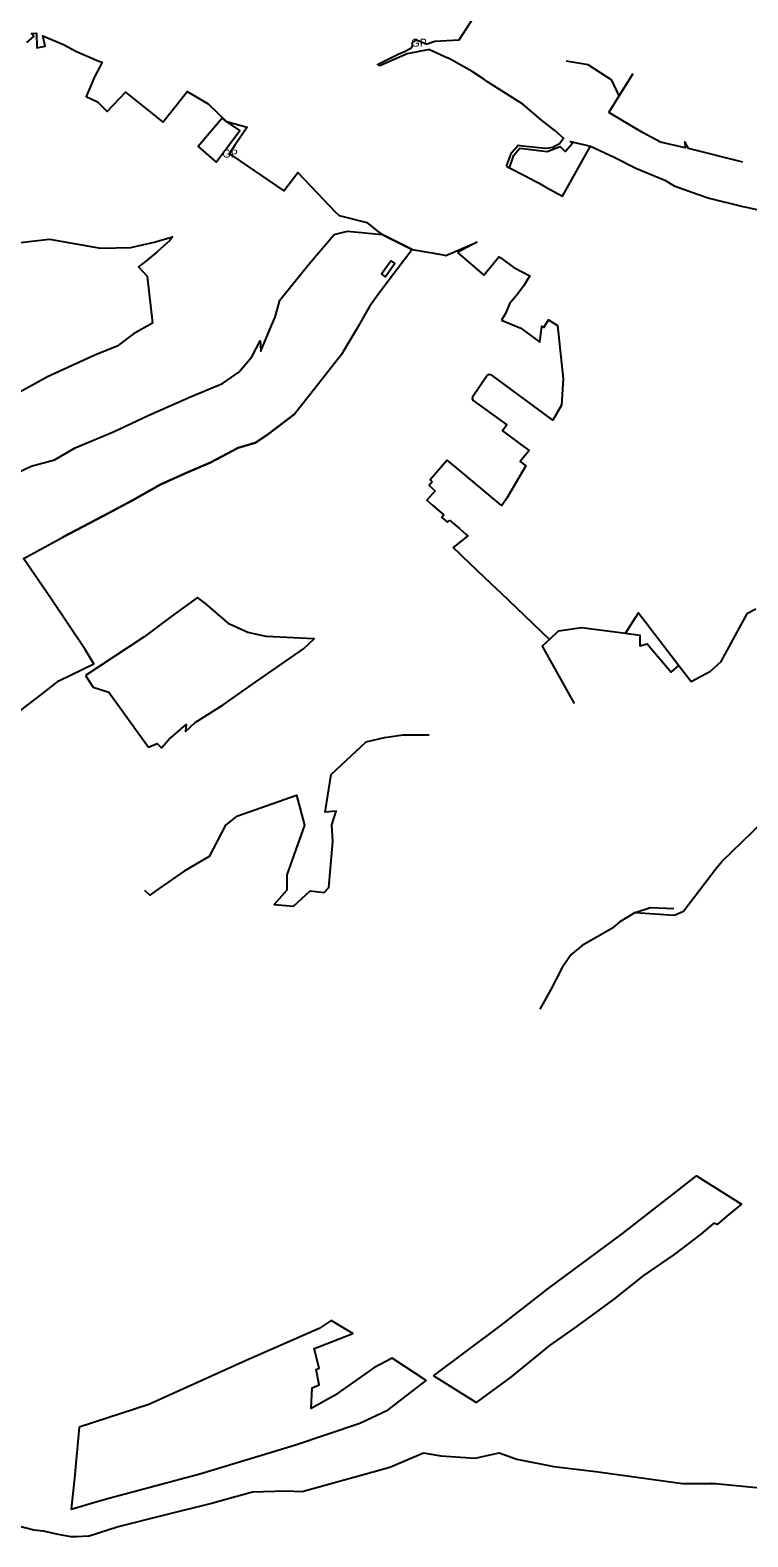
# Model space of a CAD drawing. Extents: x -617038 to -609441, y -1109294 to -1104285.
# Drawn here: x -614251 to -613353, y -1108912 to -1107029 of the extents above; entities that cross this region are included whole.
import ezdxf

# ---------------------------------------------------------------- set-up
doc = ezdxf.new("R2010")
doc.units = 0
for name, color, linetype in [('BOD_SET', 7, 'Continuous'), ('GRA_ZV', 7, 'Continuous'), ('LES_ZV', 7, 'Continuous'), ('OVNE_PRE', 7, 'Continuous'), ('OVNE_SET', 7, 'Continuous'), ('OVNI_PRE', 7, 'Continuous'), ('OVNI_SET', 7, 'Continuous')]:
    doc.layers.add(name, color=color, linetype=linetype)

msp = doc.modelspace()

# ---------------------------------------------------------------- linework, layer by layer
at = {"layer": 'BOD_SET'}
for p, q in [((-613398.7, -1108845.2), (-613397.7, -1108846.2)), ((-613398.7, -1108846.2), (-613397.7, -1108845.2)), ((-613997, -1108862.2), (-613996, -1108863.2)), ((-613997, -1108863.2), (-613996, -1108862.2))]:
    msp.add_line(p, q, dxfattribs=at)
at = {"layer": 'GRA_ZV'}
msp.add_line((-613772.9, -1107303.5), (-613810.3, -1107284.9), dxfattribs=at)
for points in [[(-613651.2, -1107201.3), (-613645.7, -1107185.5), (-613638.3, -1107177), (-613603.8, -1107180.9), (-613587.7, -1107174.8), (-613581.2, -1107181), (-613572.1, -1107170.6), (-613574.6, -1107168.4), (-613549.9, -1107174.4)], [(-613651.2, -1107201.3), (-613631.4, -1107211.5), (-613618.8, -1107218.2), (-613614.7, -1107220.4), (-613607.6, -1107224.6), (-613595.7, -1107231.1), (-613584.8, -1107237), (-613549.9, -1107174.4)], [(-614124.8, -1107300.9), (-614095.3, -1107294.4), (-614072.7, -1107287.9), (-614075.7, -1107292.2), (-614091.9, -1107306.5), (-614103.9, -1107316.5), (-614104.1, -1107316.7), (-614114.9, -1107325.3), (-614104.4, -1107337), (-614097.5, -1107395.5), (-614121.2, -1107409.1), (-614141.8, -1107424.2), (-614169.6, -1107435.4), (-614228.7, -1107462.6), (-614284, -1107493), (-614317.4, -1107507.8), (-614348.5, -1107523.2), (-614355.3, -1107445.9), (-614385, -1107362.8)], [(-614249.3, -1107574.4), (-614220.3, -1107566.5), (-614194.3, -1107551.4), (-614145.6, -1107530.8), (-614103, -1107511.2), (-614049.2, -1107487.4), (-614009.9, -1107470.9), (-613989.5, -1107457), (-613973.2, -1107437.5), (-613962.7, -1107417.8), (-613962.2, -1107430.5), (-613948.7, -1107398.4), (-613944.3, -1107388), (-613938.1, -1107366.9), (-613901.7, -1107321.4), (-613870.3, -1107284.6), (-613853.6, -1107280.7), (-613810.3, -1107284.9)], [(-614385, -1107362.8), (-614357.8, -1107344.4), (-614321.6, -1107319.4), (-614303.3, -1107308.5), (-614263.2, -1107294.7), (-614226.4, -1107290.8), (-614162.4, -1107301.9), (-614124.8, -1107300.9)], [(-613772.9, -1107303.5), (-613811.8, -1107355.2), (-613826.1, -1107374.8), (-613841.6, -1107402)], [(-613811, -1107334.1), (-613799.5, -1107317.6), (-613794.5, -1107320.9), (-613806, -1107337.6), (-613811, -1107334.1)], [(-613841.6, -1107402), (-613861.2, -1107434.9), (-613894.7, -1107477.2), (-613920.1, -1107509.3), (-613954.6, -1107535.6), (-613969, -1107545), (-613990.3, -1107551.4), (-614024.9, -1107569.6), (-614054.2, -1107582.3), (-614087.7, -1107597.1), (-614122.3, -1107616.8), (-614159.8, -1107636.6), (-614209.6, -1107663)], [(-614313, -1107860.8), (-614319, -1107819.2), (-614325.7, -1107759.9), (-614327.7, -1107742.8), (-614328.3, -1107737.2), (-614331.9, -1107705.2), (-614344, -1107630.5), (-614305.7, -1107604), (-614277.2, -1107587.8), (-614249.3, -1107574.4)], [(-614313, -1107860.8), (-614284.8, -1107896.9), (-614248.1, -1107868.5), (-614241.5, -1107863.4), (-614214.8, -1107842.7), (-614171, -1107821.3), (-614181.8, -1107803.4), (-614224.9, -1107738.9), (-614258.9, -1107689.8), (-614255.5, -1107688), (-614209.6, -1107663)], [(-614181.3, -1107835.8), (-614171.7, -1107850.6), (-614152.2, -1107856.8), (-614102.5, -1107925.4), (-614091.5, -1107921.1), (-614086.4, -1107926.2), (-614077.3, -1107915.8), (-614055.4, -1107897.3), (-614056.3, -1107906.1), (-614044.2, -1107894.7), (-614009.1, -1107872.4), (-613968.3, -1107843.9), (-613908.8, -1107802.4), (-613895.4, -1107790.2), (-613955.3, -1107787.3), (-613978.2, -1107782.3), (-614001.1, -1107771.7), (-614031.4, -1107746.1), (-614041.2, -1107738.6), (-614074.8, -1107762.7), (-614107.8, -1107787.5), (-614181.3, -1107835.8)], [(-613746.2, -1108711.3), (-613662, -1108648.3), (-613609, -1108607.1), (-613603.2, -1108602.6), (-613510.1, -1108533.7), (-613438.5, -1108478), (-613417.3, -1108461.3), (-613360.7, -1108496.7), (-613379, -1108511.7), (-613391.3, -1108521.8), (-613395.4, -1108520.3), (-613411.8, -1108534.1), (-613445, -1108559.3), (-613483.4, -1108585.7), (-613520.6, -1108615.3), (-613559.9, -1108643.9), (-613570.3, -1108651.5), (-613601, -1108673.2), (-613648.9, -1108712.3), (-613692.9, -1108744.5), (-613746.2, -1108711.3)], [(-614189.3, -1108775.3), (-614195.1, -1108839.2), (-614199.1, -1108877.8), (-614166.9, -1108868.2), (-614156.9, -1108865.3), (-614038.3, -1108833.4), (-613920.1, -1108797.7), (-613838.2, -1108770.2), (-613802.8, -1108753.7), (-613755.3, -1108716.9), (-613797.7, -1108689.2), (-613820.6, -1108701.3), (-613870.1, -1108735.6), (-613899, -1108752.1), (-613898, -1108726.1), (-613889.2, -1108722.5), (-613892.9, -1108703), (-613888.9, -1108701.5), (-613895.4, -1108676.8), (-613890.9, -1108675.1), (-613847.1, -1108658.1), (-613874, -1108641.9), (-613889, -1108652), (-613980.4, -1108692.1), (-614102.3, -1108747.1), (-614189.3, -1108775.3)]]:
    msp.add_lwpolyline(points, dxfattribs=at)
at = {"layer": 'LES_ZV'}
for p, q in [((-613513.9, -1107111.4), (-613496.2, -1107083.7)), ((-613526.9, -1107132.4), (-613513.9, -1107111.4)), ((-613359, -1107194.4), (-613427.3, -1107177.5))]:
    msp.add_line(p, q, dxfattribs=at)
for points in [[(-613513.9, -1107111.4), (-613523.2, -1107092.1), (-613552.8, -1107072.6), (-613580.2, -1107068.1)], [(-613427.3, -1107177.5), (-613431.8, -1107168.8), (-613431.2, -1107176.5), (-613462.2, -1107169.3), (-613484.8, -1107157.4), (-613526.9, -1107132.4)], [(-614209.6, -1107663), (-614159.8, -1107636.6), (-614122.3, -1107616.8), (-614087.7, -1107597.1), (-614054.2, -1107582.3), (-614024.9, -1107569.6), (-613990.3, -1107551.4), (-613969, -1107545), (-613954.6, -1107535.6), (-613920.1, -1107509.3)], [(-613601.1, -1107790.8), (-613610.2, -1107799.3), (-613570.3, -1107871.1)], [(-613505.9, -1107783.2), (-613488.1, -1107785.5), (-613487.9, -1107798.9), (-613478.9, -1107796.4), (-613448.8, -1107831.8), (-613439.2, -1107823.4)], [(-613991.9, -1108011.5), (-613917.4, -1107985.5), (-613907.5, -1108022.9), (-613929.4, -1108085.1), (-613929.4, -1108104), (-613945.2, -1108121.9), (-613921.3, -1108124), (-613900.5, -1108105.1), (-613882.9, -1108107.3), (-613877, -1108100.7), (-613872, -1108043.3), (-613873.2, -1108022.7), (-613868, -1108005.4), (-613881.4, -1108006.9), (-613873.9, -1107959.7), (-613830.5, -1107919), (-613807.5, -1107913.2), (-613784.2, -1107909.9), (-613774.4, -1107910), (-613751.6, -1107910.2)], [(-613991.9, -1108011.5), (-614006.3, -1108022.8), (-614026.7, -1108062.3), (-614058.1, -1108080.4), (-614089, -1108102), (-614096.1, -1108107.1), (-614099, -1108109.2)], [(-613493.8, -1108132.3), (-613444.7, -1108135.3), (-613433.4, -1108130.4), (-613393.4, -1108077.9), (-613385.5, -1108068.5), (-613333.6, -1108018.2)], [(-614099, -1108109.2), (-614100.9, -1108110.6), (-614107.2, -1108104.4)], [(-613493.8, -1108132.3), (-613513.1, -1108143.8), (-613523.2, -1108152), (-613560.2, -1108173.4), (-613574.5, -1108185.1), (-613585.7, -1108201.6), (-613599.2, -1108228.4), (-613612.9, -1108252.7)], [(-613493.8, -1108132.3), (-613474.7, -1108126), (-613445.7, -1108127)]]:
    msp.add_lwpolyline(points, dxfattribs=at)
at = {"layer": 'OVNE_PRE'}
for points in [[(-614178.1, -1108911.6), (-614141.6, -1108899.8), (-614080.3, -1108884.5), (-614024.9, -1108870.8), (-613996.5, -1108862.7), (-613972.5, -1108855.9), (-613930.6, -1108854.9), (-613910.5, -1108855.5), (-613800.7, -1108825.1), (-613758.7, -1108807.5)], [(-613758.7, -1108807.5), (-613736.9, -1108811.3), (-613694, -1108814.2), (-613664.1, -1108807.3), (-613641.8, -1108815.1), (-613595.5, -1108824.5), (-613560.4, -1108828.7), (-613540, -1108831.2), (-613434.6, -1108845.7), (-613398.2, -1108845.7), (-613393.4, -1108845.7), (-613316.5, -1108853.3)], [(-614234, -1108905.2), (-614245.8, -1108903.9), (-614283.2, -1108894.6)]]:
    msp.add_lwpolyline(points, dxfattribs=at)
at = {"layer": 'OVNE_SET'}
msp.add_line((-614215.6, -1108909.3), (-614234, -1108905.2), dxfattribs=at)
msp.add_lwpolyline([(-614178.1, -1108911.6), (-614192.4, -1108912.2), (-614199.2, -1108912.4), (-614215.6, -1108909.3)], dxfattribs=at)
at = {"layer": 'OVNI_PRE'}
for points in [[(-614004.8, -1107143.4), (-614010.5, -1107139.5), (-614040.3, -1107174.9), (-614017.8, -1107194.6), (-613988.3, -1107154.7), (-614004.8, -1107143.4)], [(-613662.8, -1107313.7), (-613645.6, -1107325.9), (-613625.7, -1107336.4), (-613633.5, -1107349.4), (-613641, -1107359.3), (-613651, -1107371.3), (-613656, -1107383.5), (-613660.9, -1107391.9)], [(-613743.8, -1107605), (-613754.3, -1107617), (-613746.9, -1107623.4)], [(-613733.2, -1107635.3), (-613735.7, -1107638.3), (-613728.5, -1107644.5), (-613726, -1107641.6)]]:
    msp.add_lwpolyline(points, dxfattribs=at)
at = {"layer": 'OVNI_SET'}
for p, q in [((-613764.1, -1107042.9), (-613754.3, -1107047.1)), ((-613752.7, -1107046.6), (-613754.3, -1107047.1)), ((-613751.1, -1107053.6), (-613727.5, -1107064.3)), ((-613654.8, -1107199.6), (-613651.2, -1107201.3)), ((-613746.9, -1107623.4), (-613734.9, -1107633.8)), ((-613734.9, -1107633.8), (-613733.2, -1107635.3))]:
    msp.add_line(p, q, dxfattribs=at)
for points in [[(-613649, -1106940.4), (-613714.2, -1107041.8), (-613744.5, -1107043.7), (-613752.7, -1107046.6)], [(-614254.5, -1107045), (-614246, -1107037.3), (-614248.9, -1107033.8), (-614242.6, -1107033.1), (-614242.3, -1107051.5), (-614231.7, -1107049.3), (-614234.9, -1107036.6), (-614208.8, -1107047.2), (-614192.6, -1107056), (-614164.5, -1107068.1), (-614160.3, -1107069.6), (-614163.4, -1107075.4), (-614169.7, -1107086.9), (-614175.3, -1107100.7), (-614180.5, -1107112.2), (-614166.5, -1107119.2), (-614154.3, -1107130.9), (-614131.2, -1107107.1), (-614095.8, -1107135.4), (-614091.8, -1107138.5), (-614084.5, -1107144.3)], [(-613772.8, -1107045.6), (-613768.6, -1107041.8), (-613764.1, -1107042.9)], [(-613772.7, -1107049.8), (-613772.3, -1107047.7), (-613772.8, -1107045.6)], [(-613751.1, -1107053.6), (-613778.9, -1107058.9), (-613813, -1107074.2), (-613816.1, -1107072.2), (-613798.5, -1107063.4), (-613790.1, -1107059.4), (-613782.3, -1107055.9)], [(-613782.3, -1107055.9), (-613774.3, -1107052), (-613772.7, -1107049.8)], [(-613654.8, -1107199.6), (-613648.6, -1107182.9), (-613640.2, -1107173.2), (-613634.9, -1107173.9), (-613610.3, -1107176.5), (-613604.5, -1107177.1), (-613597, -1107175.7), (-613588.6, -1107171.2), (-613583.3, -1107164.6), (-613594.4, -1107154.7), (-613611.3, -1107141.4), (-613634.4, -1107122), (-613678.4, -1107093.9), (-613683.3, -1107090.8), (-613697.6, -1107081.3), (-613727.5, -1107064.3)], [(-614084.5, -1107144.3), (-614068.1, -1107123.7), (-614054.2, -1107106.2), (-614028, -1107121.6), (-614004.8, -1107143.4)], [(-614004.8, -1107143.4), (-613979.1, -1107150.5), (-613993.3, -1107171.6)], [(-613997.6, -1107186.3), (-614001.6, -1107184.6), (-613993.3, -1107171.6)], [(-613651.2, -1107201.3), (-613631.4, -1107211.5), (-613618.8, -1107218.2), (-613614.7, -1107220.4), (-613607.6, -1107224.6), (-613595.7, -1107231.1), (-613584.8, -1107237), (-613549.9, -1107174.4)], [(-613549.9, -1107174.4), (-613520, -1107188), (-613493.1, -1107202), (-613456.8, -1107217.1), (-613444.9, -1107223.9), (-613415.8, -1107234.5), (-613401.3, -1107239.6), (-613359.1, -1107249.7), (-613354.6, -1107250.5), (-613334.6, -1107255.2), (-613327.6, -1107256.8), (-613325.8, -1107257.2), (-613318.7, -1107258.9), (-613315.2, -1107259.7), (-613312.1, -1107259.4)], [(-613997.6, -1107186.3), (-613933.3, -1107230.2), (-613915.7, -1107207.2), (-613868.6, -1107256.8)], [(-613868.6, -1107256.8), (-613864, -1107261), (-613855.9, -1107263.1), (-613829.5, -1107270), (-613816.1, -1107280.5), (-613810.3, -1107284.9), (-613772.9, -1107303.5), (-613735.9, -1107309.9), (-613730.7, -1107310.9), (-613691.7, -1107294.2), (-613716.2, -1107307.3)], [(-613716.2, -1107307.3), (-613683.2, -1107335.7), (-613664.3, -1107312.6), (-613662.8, -1107313.7)], [(-613590.8, -1107398.7), (-613583.7, -1107465), (-613585.9, -1107498.2), (-613596.7, -1107516.9), (-613673.3, -1107460.6), (-613676.4, -1107459.8), (-613679.1, -1107461.1), (-613697.2, -1107488.1), (-613697.9, -1107490.2), (-613696.5, -1107492.1), (-613654.4, -1107522.6), (-613659.8, -1107530.1), (-613636.7, -1107547.4), (-613626.6, -1107554.9), (-613637.5, -1107568.4), (-613630.7, -1107574.1), (-613654.4, -1107614.4), (-613660.8, -1107623.5), (-613661.3, -1107623.1), (-613719.7, -1107574.5), (-613728.9, -1107566.8), (-613750.4, -1107591.5), (-613747.6, -1107594), (-613751.4, -1107598.4), (-613743.8, -1107605)], [(-613660.9, -1107391.9), (-613637, -1107401.9), (-613612.9, -1107419.4), (-613610.4, -1107399.5), (-613608, -1107400.9), (-613605.5, -1107397), (-613602.3, -1107391.6), (-613590.8, -1107398.7)], [(-613726, -1107641.6), (-613713.6, -1107652.3), (-613705.2, -1107659.6), (-613703.3, -1107661.2), (-613721.5, -1107675.9), (-613713, -1107683.9), (-613710.2, -1107686.7), (-613674.4, -1107720.8), (-613662, -1107732.7), (-613642.3, -1107751.4), (-613601.1, -1107790.8), (-613589.8, -1107779.9), (-613560.8, -1107776.1), (-613505.9, -1107783.2), (-613489.8, -1107757.6), (-613439.2, -1107823.4), (-613423.7, -1107843.6), (-613399.8, -1107830.4), (-613386.2, -1107818.6), (-613353.3, -1107758), (-613343.1, -1107752.5)]]:
    msp.add_lwpolyline(points, dxfattribs=at)

# ---------------------------------------------------------------- texts
at = {"layer": 'OVNE_SET'}
for p in [(-613773.8, -1107050.1), (-614010.1, -1107188.6)]:
    msp.add_text('GP', height=10, dxfattribs=at).set_placement(p)

doc.saveas('drawing.dxf')
